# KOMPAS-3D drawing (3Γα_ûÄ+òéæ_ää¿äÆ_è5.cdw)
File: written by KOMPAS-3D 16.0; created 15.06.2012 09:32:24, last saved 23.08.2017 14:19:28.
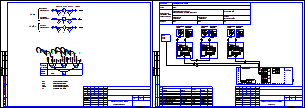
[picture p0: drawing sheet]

Sheets 1-2: A3, landscape

Title block, sheet 1: name: г. Москва, ул. Нежинская, д. 14, к.8 (кв. 1 и кв. 2); sheet number: 1; sheets: 27 / 28; sheet format: A3; stored path: D:\Проекты\Лыткарино\ул. Квартал 3А, д.25\710.74 РП.cdw; cell 320: Р
Title block, sheet 2: sheet number: 2

Views: Вид 2, Вид 3, Вид 4, Вид 5
Referenced files in C:\Program Files (x86)\ASCON\KOMPAS-3D V16\Sys\: SPDS.lcs, EngSys.lcs, GRAPHIC.LHS
Referenced files: graphic.tdp
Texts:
  МО, Клинский район, д. Решетниково, ул. Центральная, д.14
  GOST Common
  Normal
  List Paragraph
  heading 3
  для схемы
  txt
  краны
  Фоновая заливка
  Т0-элементы
  ВРУ
  Агрегат
  Системный блок  МКТС
  Среда
  Вода
  параметра и место
  отбора импульса
  Учет тепловой энергии и
  теплоносителя системы отопления
  Подающий
  трубопровод
  отопления
  Обратный
  Узел учета ХВС
  Вводной
  трубопровод ХВС
  ИМ1
  ИМ2
  ИМ3
  Плата подключений
  СБ МКТС
  Преобразователь расхода
  Термопреобразователь
  Преобразователь давления
  Преобразователь цифровой
  Системный блок МКТС
  приборы
  по месту
  шкаф
  учета
  UQIES
  УУТЭ
  Функциональная схема
  УУХВС
  Pt 100
  Преобразователь
  температуры
  давления
  UP+
  UP-
  ИМП
  Лин
  Измерительный
  модуль М121
  каб.
  Начало
  трассы
  Трассы
  Марка
  Проложен
  Датчик температуры (Т1)
  Датчик температуры (Т2)
  Датчик температуры (В1)
  Датчик давления (Т1)
  Датчик давления (В1)
  Датчик давления (Т2)
  Изм. модуль (Т1)
  Изм. модуль (Т2)
  ВРУ 220В, 50 Гц
  Изм. модуль (В1)
  ИМ1 УУТЭ
  ИМ2 УУТЭ
  ИМ1 УУХВС
  ИМ2 УУХВС
  ИМ (Т1)
  FTP
  ПВС
  Конец
  Кол-во и
  сеч. жил
  Длина,
  Размеры, параметризация
  сит. план
  подача ГВС
  обратка ГВС
  хвс
  обратка
  POLYLINE_STYLE_0.25_RGB_0_0_0
  стены
  Основная (не является границей для штриховки)
  POLYLINE_STYLE_0.18_RGB_0_0_0
  ХВС
  зеленая
  Красная тонкая
  арматура
  Подача
  Скрытая линия
  Ось Z
  Ось Y
  Ось X
  Образующая трубопровода (проектируемого)
  Трубопровод толщиной 0.6мм (одна линия)
  Трубопровод толщиной 1.2мм (одна линия)
  Трубопровод толщиной 1.0мм (одна линия)
  Трубопровод толщиной 0.8мм (одна линия)
  Трубопровод существующий (одна линия)
  Трубопровод невидимый (одна линия)
  Трубопровод демонтируемый (одна линия)
  Осевая трубопровода
  Осевая трубопровода (демонтируемого)
  Образующая трубопровода (существующего)
  Образующая трубопровода (невидимого)
  Изолированный трубопровод проектируемый (одна линия)
  Изолированный трубопровод существующий (одна линия)
  Образующая изоляции
  Изоляция
  Изолированный трубопровод невидимый (одна линия)
  Штрих пвс 075
  штрих пвс 2,5
  существующее оборудование
  Существующее оборудование
  K5LT_BASIC_RGB_0_0_255_THICK_0.53
  POLYLINE_STYLE_1.51_RGB_0_0_255
  POLYLINE_STYLE_0.50_RGB_128_128_128
  K5LT_AXLED_RGB_255_128_0_SC_1_THICK_0.18
  ACAD_ISO04W100_RGB_0_0_0_SC_1_THICK_0.18
  тонкая черная
  пломбировка
  Провода
  синий штрих
  Стили документа
  G2co
  расход вторичной воды объемный
  расход вторичной воды объемный при 70гр
  Gco
  расход теплоносителя массовый
  расход теплоносит объемн подающ
  расход теплоносит объемн обр
  Лапир
  Ghvs
  Im1
  Im2
  Im3
  Im4
  Im5
  Khvs
  норматив ХВС
  число подъездов
  число этажей
  Nkv
  число квартир
  тепловая нагрузка на отопление
  сумма Q
  Qgvs
  тепловая нагрузка ГВС
  тепловая нагрузка на циркуляцию ГВС
  иммитовставка или под манометр
  ro1
  ro2
  ro3
  ro4
  верх предел темп граф
  нижн предел темп граф
  темп подачи ГВС
  темп обр ГВС
  темр хол воды
  vzdh
  Kchn
  Ktp
  Knp
  beta
  tnv
  Vклап
  KLP
  RPD
  RDS
  PUMP
  ro5
  Переход К-76 x 3-38 x 2-09Г2С ГОСТ 17378-2001
  Переход ГОСТ 17378-2001
  Переход
  ГОСТ
  Сталь 09Г2С ГОСТ 19281-89
  Переход К-76 x 3-45 x 2,5-09Г2С ГОСТ 17378-2001
  Переход К-57 x 3-38 x 2-09Г2С ГОСТ 17378-2001
  Переход К-57 x 3-32 x 2-09Г2С ГОСТ 17378-2001
  Втулка 20x50
  Переход К-108 x 4-57 x 3-09Г2С ГОСТ 17378-2001
  Переход К-45 x 2,5-32 x 2-09Г2С ГОСТ 17378-2001
  Переход К-89 x 3,5-45 x 2,5-09Г2С ГОСТ 17378-2001
  Переход К-133 x 5-108 x 4-09Г2С ГОСТ 17378-2001
  Переход К-159 x 4,5-89 x 3,5-09Г2С ГОСТ 17378-2001
  Переход К-45 x 2,5-38 x 2-09Г2С ГОСТ 17378-2001
  Фланец 1-32-1 Ст3сп ГОСТ 12820-80
  Фланцы
  Фланец
  квадратный
  Ст3сп
  Ст3сп ГОСТ 380-2005
  Переход К-57 x 3-45 x 2,5-09Г2С ГОСТ 17378-2001
  Переход К-76 x 3-57 x 3-09Г2С ГОСТ 17378-2001
  Фланец 1-50-16 Ст3сп ГОСТ 12821-80
  Переход К-89 x 3,5-76 x 3,5-09Г2С ГОСТ 17378-2001
  Переход К-108 x 4-89 x 3,5-09Г2С ГОСТ 17378-2001
  Тройник 159 x 4,5-09Г2С ГОСТ 17376-2001
  Тройники ГОСТ 17376-2001
  Тройник
  Отвод 90-159 x 4-09Г2С ГОСТ 17375-2001
  Отвод ГОСТ 17375-2001
  Отвод
  Переход К-108 x 4-76 x 3,5-09Г2С ГОСТ 17378-2001
  Переход К-159 x 4,5-108 x 4-09Г2С ГОСТ 17378-2001
  Переход К-133 x 5-76 x 3,5-09Г2С ГОСТ 17378-2001
  Переход К-133 x 4-89 x 3,5-09Г2С ГОСТ 17378-2001
  Переход К-1-42,4 x 2,6-21,3 x 2-TS10 ГОСТ 17378-2001
  TS10
  Сталь TS10 ИСО 2604/2-75
  Фланец 1-20-16 Ст3сп ГОСТ 12820-80
  Лит-Масса-Масштаб
  Материал-Предприятие
  Title Specification
  Body Specification ( left align )
  Body Specificaton ( centered )
  Поз.
  Кол.
  Приме-
  чание
  Таблица спецификации
  Засыпка
  Штрих3
  Штрих2
  Штрих1
  Песок
  Штр0.5пр7
  Штр0.5пр12
  Штр0.3пр10
  Штр1.4пр21.21
  Штр1пр15
  Штр2.12пр35
  Штр1.5пр25
  Штр2.82пр42.42
  Штр2пр30
  SACNCR_ISO 1
  Электрощитовая
  Пр-1
  Ок-1
  вапвыапвы
  Обозначение стандарта
  Типоразмер
  Разраб.
  Пров.
  Т.контр.
  Н.контр.
  Утв.
  автоматизации
  Рабочие чертежи основного комплекта. ГОСТ Р 21.1101-2009 Ф3
  Стадия
  Лист
  Листов
  Изм.
  Кол.уч.
  №док.
  Подп.
  Дата
  Изменение
  Номер документа
  Подпись
  Наименование объекта строительства, в состав которого входит здание, наим. микр
  Наименование здания (сооружения)
  Порядковый номер листа
  Количество листов в документе
  Наименование изображения
  Индекс предприятия, выпускающего документ
  Инв. № подл.
  Подп. и дата
  Взам. инв. №
  Инвентарный номер подлинника
  Подпись принявшего подлинник на хранение
  Инвентарный номер подлинника, взамен которого выпущен данный подлинник
  Согласовано
  Формат листа
  Согласование
  03 Рабочие чертежи основного комплекта. ГОСТ Р 21.1101-2009 Ф3
  Схема соединений внешних
  проводок
Dimensions and other numbers on the sheet: 0; 220В; 50Гц; 1; 2; 3; 6; 5; 4; 13; 1,2,3; 4,5,6; 7,8,9; 10,11,12; 8; 10; 11; 7; 12; 4,0; 2,6582; 0,0160; 16; 95; 2,6160; 3,0; 70; 9; 0,0; 0,0000; 4-20; 2x2x0,52; 3х0,75; 15; 25; 14; 09Г2С; 17; 19; 20; 21; 22; 23; 24; 26; 30; 31; 33; 34; 52; 64; 65; 66; 67; 69; 71; 72; 73; 74; 75; 27; 28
